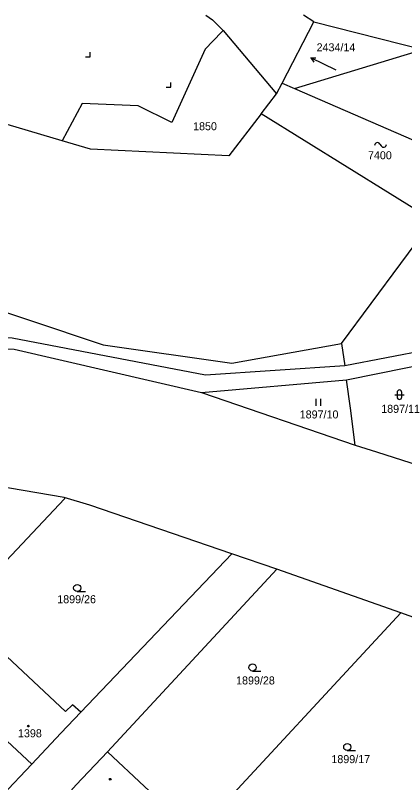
# Model space of a CAD drawing. Extents: x -667048 to -665920, y -1108425 to -1107247.
# Drawn here: x -666222.3 to -666139.7, y -1107411.8 to -1107249 of the extents above; entities that cross this region are included whole.
import ezdxf

# ---------------------------------------------------------------- set-up
doc = ezdxf.new("R2010")
doc.units = 0
for name, color, linetype in [('Default', 7, 'Continuous'), ('Hranice parcel', 7, 'Continuous'), ('Parcelní čísla', 7, 'Continuous'), ('Značky budov', 7, 'Continuous'), ('Značky kultur', 7, 'Continuous')]:
    doc.layers.add(name, color=color, linetype=linetype)

# ---------------------------------------------------------------- blocks, each defined once
blk = doc.blocks.new('8.021')
at = {"layer": 'Default'}
for p, q in [((3018, -10), (2039, 490)), ((-2982, -10), (3018, -10)), ((3018, -10), (2039, -510))]:
    blk.add_line(p, q, dxfattribs=at)
blk = doc.blocks.new('3.041')
at = {"layer": 'Default'}
blk.add_line((8, 0), (1758, 0), dxfattribs=at)
blk.add_circle((8, 750), 750, dxfattribs=at)
blk = doc.blocks.new('3.191')
at = {"layer": 'Default'}
for p, q in [((-1000, 0), (0, 0)), ((0, 0), (0, 1000))]:
    blk.add_line(p, q, dxfattribs=at)
blk = doc.blocks.new('4.021')
at = {"layer": 'Default'}
blk.add_circle((-7, 1), 175, dxfattribs=at)
blk = doc.blocks.new('3.161')
at = {"layer": 'Default'}
for p, q in [((-1000, 1000), (1000, 1000)), ((-500, 1500), (-500, 500)), ((500, 500), (500, 1500))]:
    blk.add_line(p, q, dxfattribs=at)
for centre, start, end in [((0, 1500), 0, 180), ((0, 500), 180, 359.98789)]:
    blk.add_arc(centre, 500, start, end, dxfattribs=at)
blk = doc.blocks.new('3.061')
at = {"layer": 'Default'}
for p, q in [((-511, -1), (-511, 1499)), ((489, -1), (489, 1499))]:
    blk.add_line(p, q, dxfattribs=at)
blk = doc.blocks.new('4.241')
at = {"layer": 'Default'}
blk.add_line((-150, 200), (150, -200), dxfattribs=at)
for centre, start, end in [((-662.5, -87.5), 29.291362, 181.218875), ((662.5, 87.5), 209.291362, 1.218875)]:
    blk.add_arc(centre, 587.6, start, end, dxfattribs=at)

msp = doc.modelspace()

# ---------------------------------------------------------------- linework, layer by layer
at = {"layer": 'Hranice parcel'}
for points in [[(-666181.83, -1107248.98), (-666180.44, -1107249.93), (-666178.18, -1107252.2)], [(-666158.97, -1107250.39), (-666161.16, -1107248.98)], [(-666165.67, -1107263.35), (-666158.97, -1107250.39)], [(-666158.97, -1107250.39), (-666135.82, -1107256.22)], [(-666178.18, -1107252.2), (-666178.53, -1107252.55), (-666181.99, -1107256.14), (-666189.05, -1107271.75), (-666196.19, -1107268.16), (-666208.1, -1107267.69), (-666212.31, -1107275.63)], [(-666178.18, -1107252.2), (-666166.85, -1107265.64)], [(-666163.06, -1107264.49), (-666135.82, -1107256.22)], [(-666166.85, -1107265.64), (-666165.67, -1107263.35)], [(-666165.67, -1107263.35), (-666163.06, -1107264.49)], [(-666170.11, -1107269.86), (-666166.85, -1107265.64)], [(-666163.06, -1107264.49), (-666114.71, -1107285.52), (-666117.01, -1107287.33)], [(-666170.11, -1107269.86), (-666176.99, -1107278.77), (-666206.3, -1107277.4), (-666212.31, -1107275.63)], [(-666133.6, -1107292.51), (-666170.11, -1107269.86)], [(-666212.31, -1107275.63), (-666224.03, -1107272.17)], [(-666153.04, -1107318.64), (-666134.21, -1107293.18), (-666133.6, -1107292.51)], [(-666302.94, -1107296.96), (-666273.03, -1107298.79), (-666259.3, -1107304.5), (-666235.37, -1107308.27), (-666203.62, -1107318.94), (-666176.32, -1107322.78), (-666153.04, -1107318.64)], [(-666152.4, -1107323.34), (-666181.96, -1107325.37), (-666222.91, -1107317.47), (-666252.62, -1107316.38)], [(-666421.62, -1107366.12), (-666414.63, -1107364.57), (-666389.01, -1107349.02), (-666368.67, -1107338.48), (-666320.24, -1107322.6), (-666276.14, -1107317.79), (-666222.54, -1107319.87), (-666182.81, -1107329.06)], [(-666125.26, -1107317.7), (-666125.87, -1107318.29), (-666152.4, -1107323.34)], [(-666153.04, -1107318.64), (-666152.4, -1107323.34)], [(-666152, -1107326.31), (-666126.48, -1107321.18)], [(-666182.81, -1107329.06), (-666152, -1107326.31)], [(-666150.17, -1107340.2), (-666151.17, -1107332.39), (-666152, -1107326.31)], [(-666182.81, -1107329.06), (-666150.17, -1107340.2)], [(-666150.17, -1107340.2), (-666145.64, -1107341.64), (-666134.85, -1107345.07)], [(-666211.93, -1107351.31), (-666240.95, -1107346.35), (-666252, -1107345.83)], [(-666211.93, -1107351.31), (-666211.87, -1107351.61), (-666243.43, -1107385.11)], [(-666176.31, -1107363.27), (-666206.5, -1107352.92), (-666211.93, -1107351.31)], [(-666176.31, -1107363.27), (-666208.34, -1107396.85)], [(-666166.77, -1107366.53), (-666176.31, -1107363.27)], [(-666202.75, -1107405.28), (-666166.77, -1107366.53)], [(-666140.49, -1107375.81), (-666166.77, -1107366.53)], [(-666140.49, -1107375.81), (-666183.97, -1107422.77)], [(-666113.67, -1107385.26), (-666113.91, -1107385.35), (-666140.49, -1107375.81)], [(-666208.34, -1107396.85), (-666210.13, -1107395.35), (-666211.63, -1107396.75), (-666224.09, -1107385.09), (-666226.88, -1107388.25), (-666233, -1107394.76)], [(-666218.8, -1107407.91), (-666226.21, -1107401.04), (-666229.93, -1107397.6), (-666231.97, -1107395.71)], [(-666208.34, -1107396.85), (-666212.62, -1107401.33), (-666218.8, -1107407.91)], [(-666210.52, -1107413.58), (-666209.33, -1107412.3), (-666202.75, -1107405.28)], [(-666183.97, -1107422.77), (-666185.88, -1107420.99), (-666194.9, -1107412.63), (-666202.75, -1107405.28)], [(-666218.8, -1107407.91), (-666225.07, -1107414.6), (-666227.75, -1107417.46)]]:
    msp.add_lwpolyline(points, dxfattribs=at)

# ---------------------------------------------------------------- block references
at = {"layer": 'Značky budov', "xscale": 0.0010000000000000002, "yscale": 0.0010000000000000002}
for name, p in [('4.241', (-666144.81, -1107276.49)), ('4.021', (-666219.49, -1107399.85)), ('4.021', (-666202.13, -1107411.11))]:
    msp.add_blockref(name, p, dxfattribs=at)
at = {"layer": 'Značky kultur', "xscale": 0.0010000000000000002, "yscale": 0.0010000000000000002}
for name, p in [('3.191', (-666206.4, -1107257.81)), ('3.191', (-666189.26, -1107264.26)), ('3.161', (-666140.79, -1107330.5)), ('3.061', (-666157.97, -1107331.87)), ('3.041', (-666209.16, -1107371.27)), ('3.041', (-666171.96, -1107388.15)), ('3.041', (-666151.87, -1107405.03))]:
    msp.add_blockref(name, p, dxfattribs=at)
at = {"layer": 'Značky kultur', "xscale": 0.0010000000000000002, "yscale": 0.0010000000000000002, "rotation": 154.00000006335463}
msp.add_blockref('8.021', (-666156.89, -1107259.34), dxfattribs=at)

# ---------------------------------------------------------------- texts
at = {"layer": 'Parcelní čísla'}
for s, p in [('2434/14', (-666158.36, -1107256.62)), ('1850', (-666184.56, -1107273.37)), ('7400', (-666147.46, -1107279.53)), ('1897/10', (-666161.94, -1107334.54)), ('1897/11', (-666144.65, -1107333.35)), ('1899/26', (-666213.38, -1107373.76)), ('1899/28', (-666175.44, -1107391)), ('1398', (-666221.71, -1107402.21)), ('1899/17', (-666155.22, -1107407.7))]:
    msp.add_text(s, height=1.7, dxfattribs=at).set_placement(p)

doc.saveas('drawing.dxf')
